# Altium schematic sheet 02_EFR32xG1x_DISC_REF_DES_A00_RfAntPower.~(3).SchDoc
size 420 x 297 mm
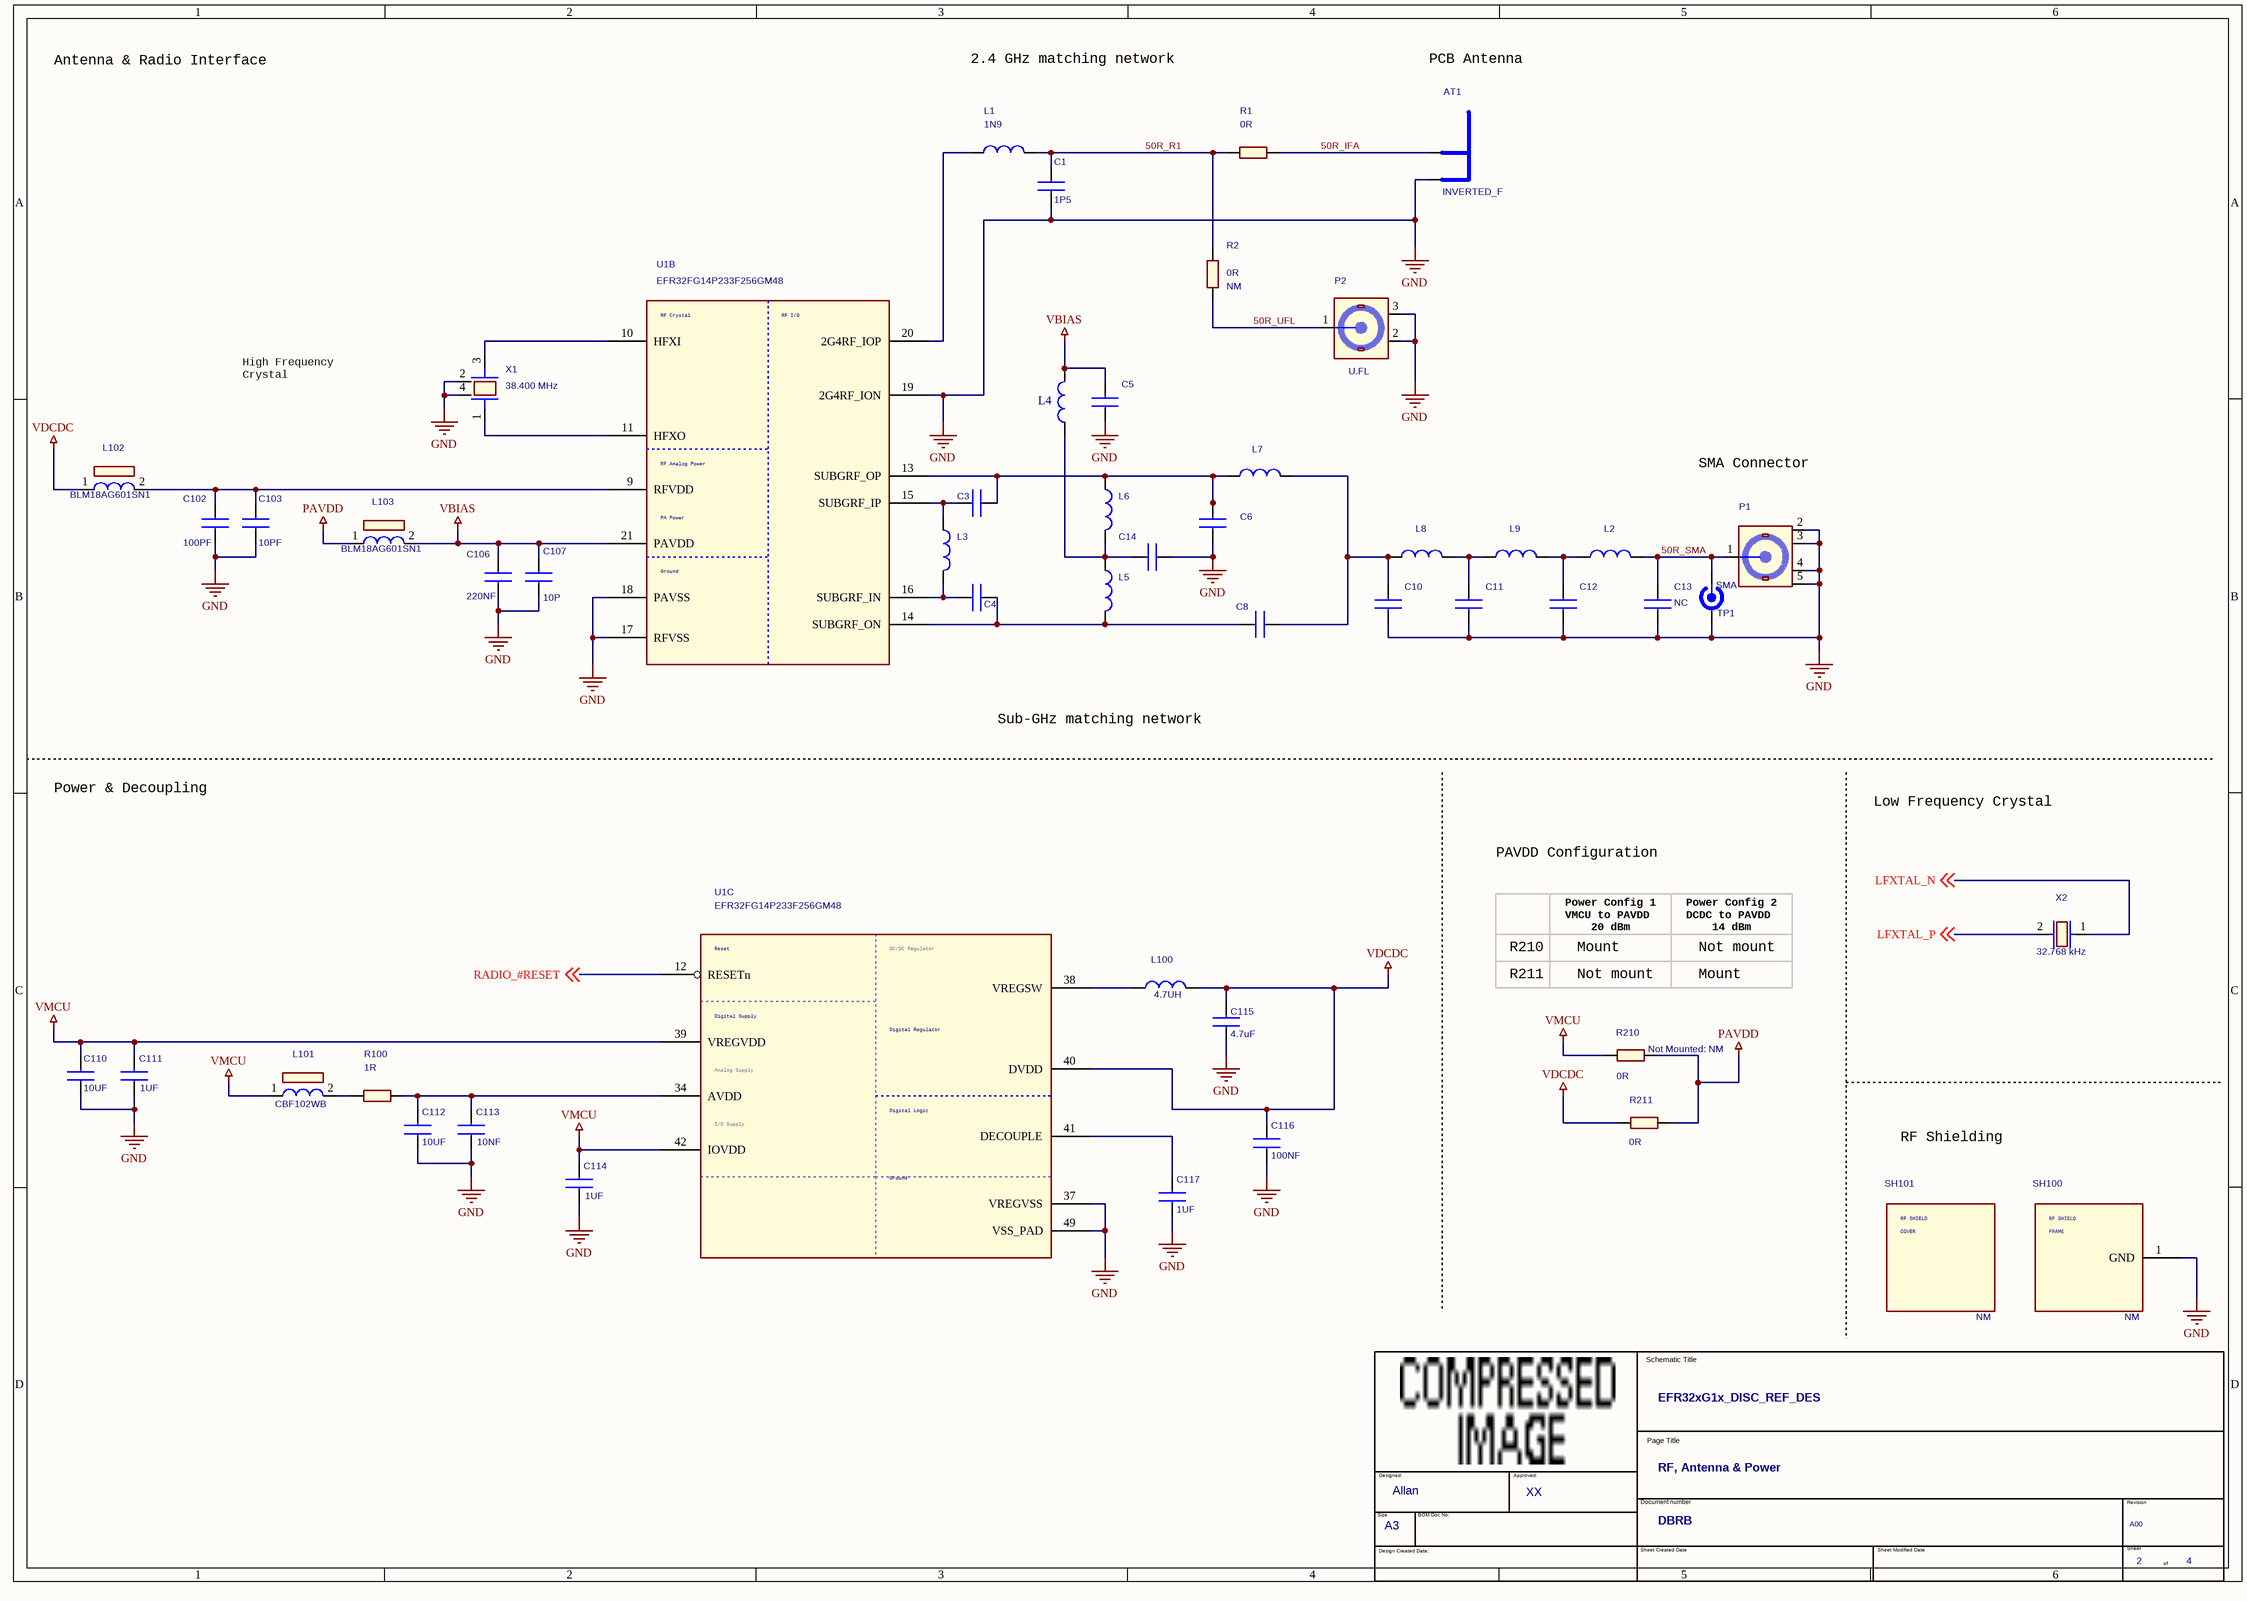
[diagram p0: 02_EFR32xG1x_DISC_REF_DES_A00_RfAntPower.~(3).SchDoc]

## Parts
*  OrgAddr2: XX  OrgAddr1: Allan  Page Count: 4  Page Number: 2  Doc: DBRB  Title: EFR32xG1x_DISC_REF_DES  RevCode: A00  Page Size: A3  Page Title: RF, Antenna & Power  (hidden comment: TitleBlock_EnergyMicro_A3)  (graphical)
AT1  INVERTED_F  [ANT_INV_F_2.4_GHZ_17.3MM_MIR]
C1  1P5  [C0201_L]
C3  1P8  [C0201_L]  (value not drawn)
C4  1P8  [C0201_L]  (value not drawn)
C5  270pF  [C0201_L]  (value not drawn)
C6  5.1P  [C0201_L]  (value not drawn)
C8  4P7  [C0201_L]  (value not drawn)
C10  6P2  [C0201_L]  (value not drawn)
C11  5.6P  [C0201_L]  (value not drawn)
C12  5P6  [C0201_L]  (value not drawn)
C13  NC  [C0201_L]
C14  2P  [C0201_L]  (value not drawn)
C102  100PF  [C0402_L]
C103  10PF  [C0402_L]
C106  220NF  [C0402_L]
C107  10P  [C0201_L]
C110  10UF  [C0603_L]
C111  1UF  [C0402_L]
C112  10UF  [C0603_L]
C113  10NF  [C0402_L]
C114  1UF  [C0402_L]
C115  4.7uF  [C0402_L]
C116  100NF  [C0402_L]
C117  1UF  [C0402_L]
L1  1N9  [COIL_0201_L]
L2  120P  [COIL_0201_L]  (value not drawn)
L3  75NH  [COIL_0201_L]  (value not drawn)
L4  330NH  [COIL_0402_L]  (value not drawn)
L5  12NH  [COIL_0201_L]  (value not drawn)
L6  12NH  [COIL_0201_L]  (value not drawn)
L7  27NH  [COIL_0201_L]  (value not drawn)
L8  24NH  [COIL_0201_L]  (value not drawn)
L9  24NH  [COIL_0201_L]  (value not drawn)
L100  4.7UH  [COIL_MUR_LQH3NP_1212]
L101  CBF102WB  [WURTH_CBF_0603]
L102  BLM18AG601SN1  [COIL_MUR_BLM18_0603]
L103  BLM18AG601SN1  [COIL_MUR_BLM18_0603]
P1  SMA  [TE_SMA_TH_1814832]
P2  U.FL  [HIROSE_U.FL-R-SMT-1]
R1  0R  [R0402_L]
R2  0R  Not Mounted: NM  [R0402_L]
R100  1R  [R0402_L]
R210  0R  Not Mounted: NM  [R0402_L]
R211  0R  [R0402_L]
SH100  Not Mounted: NM  [RF_SHIELD_FRAME_BMI-S-203-F_PCB4100]  (hidden comment: RF_SHIELD_FRAME_BMI-S-203-F)
SH101  Not Mounted: NM  (hidden comment: RF_SHIELD_COVER_BMI-S-203-C)
TP1  RF_TEST_POINT  [TP_INGUN_50_OHM_CLOSED openvia]  (value not drawn)
U1  EFR32FG14P233F256GM48  [QFN48_M050_SQ7.0_EP_SL_L]  (parts B,C of 3)
X1  38.400 MHz  [X_SSS_DSX211SH_2.05X1.65-4]
X2  32.768 kHz  [X_MCS_CM8V-T1A]

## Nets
GND: AT1.2(GND) C1.1 C5.2 C6.2 C10.2 C11.2 C12.2 C13.2 C14.2 C102.2 C103.2 C106.2 C107.2 C110.2 C111.2 C112.2 C113.2 C114.2 C115.2 C116.2 C117.2 P1.2(GND1) P1.3(GND2) P1.4(GND3) P1.5(GND4) P2.2(GND1) P2.3(GND4) SH100.1(GND) TP1.2(GND) U1.17(RFVSS) U1.18(PAVSS) U1.19(2G4RF_ION) U1.37(VREGVSS) U1.49(VSS_PAD) X1.2 X1.4
PAVDD: L103.1 R210.1 R211.1
VBIAS: C5.1 C106.1 C107.1 L4.1 L103.2 U1.21(PAVDD)
VDCDC: C115.1 C116.1 L100.2 L102.1 R211.2 U1.40(DVDD)
VMCU: C110.1 C111.1 C114.1 L101.1 R210.2 U1.39(VREGVDD) U1.42(IOVDD)
50R_IFA: AT1.1(ANT) R1.2
50R_R1: C1.2 L1.2 R1.1 R2.1
50R_SMA: C13.1 L2.1 P1.1(SIGNAL) TP1.1(RF)
50R_UFL: P2.1(SIGNAL) R2.2
LFXTAL_N: X2.1 ; off-sheet LFXTAL_N
LFXTAL_P: X2.2 ; off-sheet LFXTAL_P
RADIO_#RESET: U1.12(RESETn) ; off-sheet RADIO_#RESET
NetC3_1: C3.1 C6.1 L6.1 L7.2 U1.13(SUBGRF_OP)
NetC3_2: C3.2 L3.1 U1.15(SUBGRF_IP)
NetC4_1: C4.1 C8.2 L5.2 U1.14(SUBGRF_ON)
NetC4_2: C4.2 L3.2 U1.16(SUBGRF_IN)
NetC8_1: C8.1 C10.1 L7.1 L8.2
NetC11_1: C11.1 L8.1 L9.2
NetC12_1: C12.1 L2.2 L9.1
NetC14_1: C14.1 L4.2 L5.1 L6.2
NetC102_1: C102.1 C103.1 L102.2 U1.9(RFVDD)
NetC112_1: C112.1 C113.1 R100.2 U1.34(AVDD)
NetC117_1: C117.1 U1.41(DECOUPLE)
NetL1_1: L1.1 U1.20(2G4RF_IOP)
NetL100_1: L100.1 U1.38(VREGSW)
NetL101_2: L101.2 R100.1
NetU1_10: U1.10(HFXI) X1.3
NetU1_11: U1.11(HFXO) X1.1

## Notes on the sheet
- Antenna & Radio Interface
- 2.4 GHz matching network
- PCB Antenna
- High Frequency
  Crystal
- SMA Connector
- Sub-GHz matching network
- Power & Decoupling
- PAVDD Configuration
- Low Frequency Crystal
- Power Config 1
  VMCU to PAVDD
  20 dBm
- Power Config 2
  DCDC to PAVDD
  14 dBm
- R210
- R211
- Not mount
- Mount
- RF Shielding

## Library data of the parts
AT1 = ANT_INVERTED_F
C1 = C0402: Tolerance: ?.05P; Mfg: Murata; Mfg #: GRM1555C1H1R5WA01D
C3 C4 = C0402: Tolerance: ?.05P; Mfg: Murata; Mfg #: GRM1555C1H1R6WA01D
C5 C10 = C0402: Tolerance: ?.1P; Mfg: Murata; Mfg #: GRM1555C1H6R2BA01D
C6 = C0402
C8 C14 = C0402: Tolerance: ?%; Mfg: Murata; Mfg #: GRM1555C1H271FA01D
C11 = C0402: Tolerance: ?%; Mfg: Murata; Mfg #: GRM1555C1H110GA01D
C12 C13 = C0402: Tolerance: ?.05pF; Mfg: Murata; Mfg #: GRM1555C1H5R6WA01D
C102 C103 C107 = C0402: Rating: 50V; Tolerance: 5%
C106 C113 C116 = C0402: Rating: 16V; Tolerance: 10%
C110 C112 = C0603: Rating: 6.3V; Tolerance: 20%
C111 C114 C117 = C0402: Rating: 25V; Tolerance: 10%
C115 = C0402: Rating: 6.3V; Tolerance: 10%
L1 = L0402: Mfg: Murata; Mfg #: LQP15MN1N9W02D; Tolerance: ?.05N
L2 L8 L9 = L0402: Mfg: Murata; Mfg #: LQW15AN24NG00D; Tolerance: ?%
L3 L5 L6 = L0402
L4 = L0603
L7 = L0402: Mfg: Murata; Mfg #: LQW15AN18NG00D; Tolerance: ?%
L100 = LQH3NP: Mfg: Murata; Mfg #: LQH3NPN4R7MM0L
L101 = CBF102WB: Mfg: W黵th Electronics; Mfg #: 74279266
L102 L103 = BLM18AG: Mfg: Murata; Mfg #: BLM18AG601SN1D
P1 = SMA_TH: Mfg #: 5-1814832-1; Mfg: TE Connectivity
P2 = HIROSE_U.FL: Mfg: Hirose; Mfg #: U.FL-R-SMT-1
R1 R2 R100 R210 R211 = R0402
SH100 = RF_SHIELD_FRAME_BMI-S-203-F: Mfg: Laird Technologies
SH101 = RF_SHIELD_COVER_BMI-S-203-C: Mfg: Laird Technologies
TP1 = TP_RF
U1 = EFR32-DUALBAND-QFN48: MFG: Silicon Labs; MFG #: EFR32FG14P233F256GM48-BR
X1 = DSX211SH: Mfg: KDS; Mfg #: DSX211SH 1ZZNAE38400AB0A
X2 = CM8V-T1A: Mfg: KDS; Mfg #: DST210 1TJG125DP1A0012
